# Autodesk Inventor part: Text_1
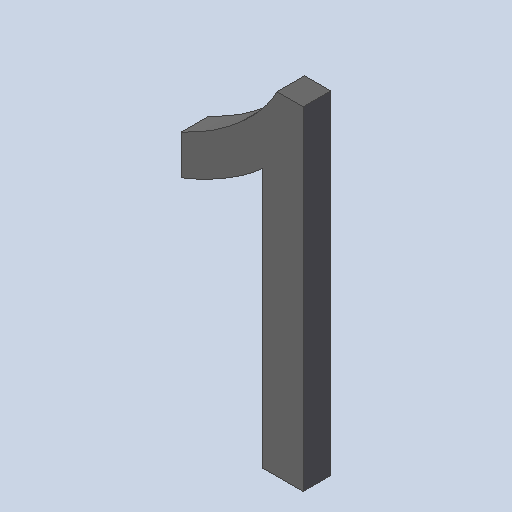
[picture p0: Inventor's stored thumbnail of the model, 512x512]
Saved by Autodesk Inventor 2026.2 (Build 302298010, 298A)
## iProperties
Created: 2026-10
Part Number: Text_1
Material: Générique
Document SubType Name: Modeling
Designer: mel
Density: 1 g/cm^3
Appearance: Par défaut
Author: mel
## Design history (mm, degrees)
feature "Base1"
node "Solide1"
